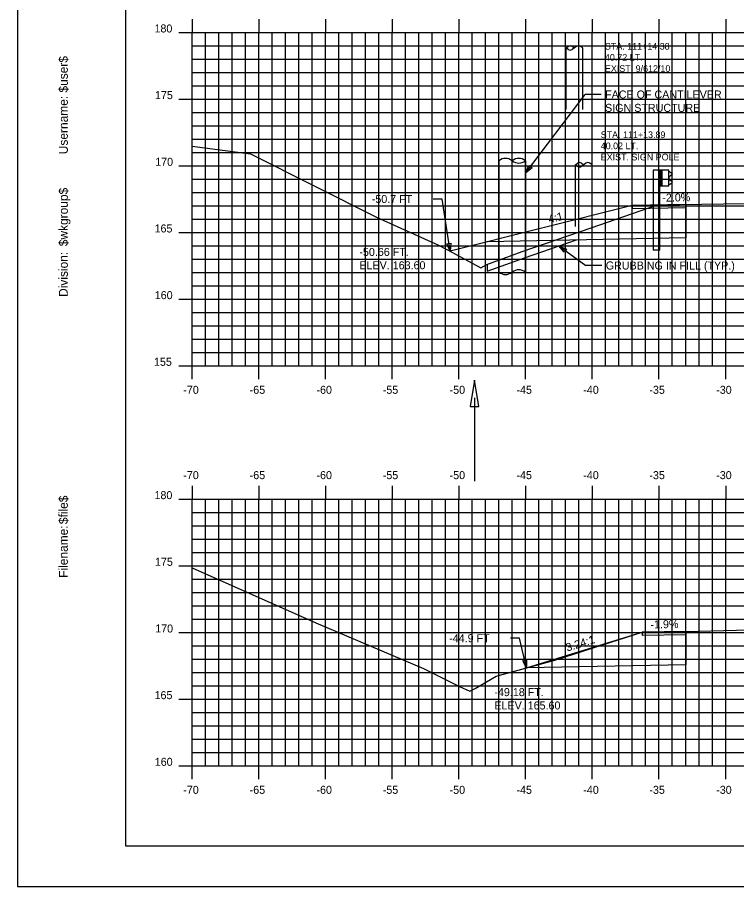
# Model space of a CAD drawing. Extents: x 1668473 to 1668643, y 337823 to 337933.
# Drawn here: x 1668472.7 to 1668526.6, y 337823.4 to 337888.6 of the extents above; entities that cross this region are included whole.
import ezdxf

# ---------------------------------------------------------------- set-up
doc = ezdxf.new("R2010")
doc.units = 0
for name, color, linetype in [('ANNOTATION', 7, 'Continuous'), ('BORDER', 7, 'Continuous'), ('D_Drainage_Ditch_Line', 7, 'Continuous'), ('D_Guardrail_Beam_Lt', 7, 'Continuous'), ('D_Roadway_Pavement', 7, 'Continuous'), ('D_Text_Monospaced', 7, 'Continuous'), ('D_Text_Standard', 7, 'Continuous'), ('Grubbing', 7, 'Continuous'), ('H_V ANNOTATION', 7, 'Continuous'), ('MAJOR', 7, 'Continuous'), ('MINOR', 7, 'Continuous'), ('PLOT BOUNDARY', 7, 'Continuous'), ('S_Roadway_Centerline', 7, 'Continuous'), ('S_Utilities_Pole_Joint', 7, 'Continuous')]:
    doc.layers.add(name, color=color, linetype=linetype)

msp = doc.modelspace()

# ---------------------------------------------------------------- linework, layer by layer
at = {"layer": 'ANNOTATION'}
for p, q in [((1668510.785, 337876.902), (1668515.247, 337882.801)), ((1668516.447, 337882.801), (1668515.247, 337882.801)), ((1668508.785, 337877.831), (1668508.785, 337869.479)), ((1668510.785, 337877.831), (1668510.785, 337869.479)), ((1668513.275, 337871.439), (1668515.297, 337869.975)), ((1668516.497, 337869.975), (1668515.297, 337869.975))]:
    msp.add_line(p, q, dxfattribs=at)
for points in [[(1668511.267, 337877.29), (1668510.785, 337876.902), (1668511.028, 337877.471)], [(1668513.673, 337870.966), (1668513.275, 337871.439), (1668513.849, 337871.209)]]:
    msp.add_lwpolyline(points, close=True, dxfattribs=at)
for centre, major_axis, start_param, end_param in [((1668509.285, 337876.346), (0, 1.664), 5.815604, 6.750767), ((1668510.285, 337876.346), (0, -1.664), 2.674011, 3.609174), ((1668510.285, 337879.317), (0, -1.664), 5.815604, 6.750767), ((1668509.285, 337870.964), (0, -1.664), 5.815604, 6.750767), ((1668510.285, 337867.994), (0, -1.664), 2.674011, 3.609174)]:
    msp.add_ellipse(centre, major_axis=major_axis, ratio=0.666667, start_param=start_param, end_param=end_param, dxfattribs=at)
at = {"layer": 'BORDER'}
for p, q in [((1668480.786, 337931.453), (1668480.786, 337826.453)), ((1668480.786, 337826.453), (1668640.786, 337826.453))]:
    msp.add_line(p, q, dxfattribs=at)
at = {"layer": 'D_Drainage_Ditch_Line'}
msp.add_line((1668506.963, 337860.055), (1668506.964, 337853.811), dxfattribs=at)
msp.add_lwpolyline([(1668506.635, 337859.399), (1668507.291, 337859.399), (1668506.963, 337861.367)], close=True, dxfattribs=at)
at = {"layer": 'D_Guardrail_Beam_Lt'}
for p, q in [((1668520.356, 337877.116), (1668520.356, 337871.116)), ((1668520.827, 337877.116), (1668520.356, 337877.116)), ((1668521.515, 337877.116), (1668520.827, 337877.116)), ((1668520.827, 337877.116), (1668520.827, 337875.949)), ((1668520.89, 337877.116), (1668520.89, 337875.949)), ((1668520.994, 337877.116), (1668520.994, 337875.949)), ((1668521.515, 337875.949), (1668521.515, 337877.116)), ((1668521.515, 337877.033), (1668521.589, 337877.018)), ((1668521.519, 337876.568), (1668521.519, 337876.498)), ((1668521.748, 337876.768), (1668521.553, 337876.632)), ((1668521.605, 337877.011), (1668521.748, 337876.911)), ((1668520.827, 337875.949), (1668521.515, 337875.949)), ((1668520.848, 337871.116), (1668520.848, 337875.949)), ((1668521.589, 337876.047), (1668521.515, 337876.033)), ((1668521.553, 337876.433), (1668521.748, 337876.297)), ((1668521.748, 337876.154), (1668521.605, 337876.054)), ((1668520.848, 337871.116), (1668520.356, 337871.116))]:
    msp.add_line(p, q, dxfattribs=at)
for centre, major_axis, start_param, end_param in [((1668521.598, 337876.568), (-0.0789, 0), 5.323254, 6.283185), ((1668521.598, 337876.498), (-0.0789, 0), 6.283185, 7.243116), ((1668521.581, 337876.977), (0.0417, 0), 0.959931, 1.376053), ((1668521.698, 337876.84), (0.0877, 0), 5.323254, 7.243116), ((1668521.581, 337876.088), (0.0417, 0), 4.907132, 5.323254), ((1668521.698, 337876.225), (0.0877, 0), 5.323254, 7.243116)]:
    msp.add_ellipse(centre, major_axis=major_axis, ratio=0.995501, start_param=start_param, end_param=end_param, dxfattribs=at)
at = {"layer": 'D_Roadway_Pavement'}
for p, q in [((1668522.785, 337874.553), (1668518.785, 337874.473)), ((1668522.785, 337874.553), (1668522.785, 337874.303)), ((1668522.785, 337874.553), (1668522.785, 337872.053)), ((1668518.785, 337874.473), (1668505.124, 337871.057)), ((1668518.785, 337874.473), (1668518.785, 337874.223)), ((1668522.785, 337874.303), (1668518.785, 337874.223)), ((1668522.785, 337872.053), (1668507.916, 337871.755)), ((1668510.845, 337839.796), (1668519.521, 337842.472)), ((1668522.785, 337842.535), (1668519.521, 337842.469)), ((1668519.521, 337842.469), (1668519.521, 337842.219)), ((1668522.785, 337842.285), (1668519.521, 337842.219)), ((1668522.785, 337842.535), (1668522.785, 337842.285)), ((1668522.785, 337842.535), (1668522.785, 337840.035)), ((1668522.785, 337840.035), (1668510.845, 337839.796))]:
    msp.add_line(p, q, dxfattribs=at)
at = {"layer": 'D_Text_Standard'}
for points in [[(1668505.124, 337871.057), (1668504.538, 337874.961), (1668503.858, 337874.961)], [(1668510.845, 337839.796), (1668510.338, 337842.026), (1668509.658, 337842.026)]]:
    msp.add_lwpolyline(points, dxfattribs=at)
for points in [[(1668505.124, 337871.057), (1668504.894, 337871.611), (1668505.181, 337871.655)], [(1668510.845, 337839.796), (1668510.574, 337840.331), (1668510.858, 337840.396)]]:
    msp.add_lwpolyline(points, close=True, dxfattribs=at)
at = {"layer": 'Grubbing'}
msp.add_line((1668507.916, 337870.074), (1668507.916, 337869.542), dxfattribs=at)
msp.add_lwpolyline([(1668507.916, 337869.542), (1668510.696, 337870.56), (1668514.593, 337871.889)], dxfattribs=at)
at = {"layer": 'MAJOR'}
for p, q in [((1668485.785, 337888.455), (1668485.785, 337887.453)), ((1668490.785, 337888.455), (1668490.785, 337887.453)), ((1668495.785, 337888.455), (1668495.785, 337887.453)), ((1668500.785, 337888.455), (1668500.785, 337887.453)), ((1668505.785, 337888.455), (1668505.785, 337887.453)), ((1668510.785, 337888.455), (1668510.785, 337887.453)), ((1668515.785, 337888.455), (1668515.785, 337887.453)), ((1668520.785, 337888.455), (1668520.785, 337887.453)), ((1668525.785, 337888.455), (1668525.785, 337887.453)), ((1668484.783, 337887.453), (1668485.785, 337887.453)), ((1668485.785, 337887.453), (1668625.785, 337887.453)), ((1668485.785, 337862.453), (1668485.785, 337887.453)), ((1668485.785, 337862.453), (1668485.785, 337887.453)), ((1668485.785, 337887.453), (1668625.785, 337887.453)), ((1668490.785, 337862.453), (1668490.785, 337887.453)), ((1668495.785, 337862.453), (1668495.785, 337887.453)), ((1668500.785, 337862.453), (1668500.785, 337887.453)), ((1668505.785, 337862.453), (1668505.785, 337887.453)), ((1668510.785, 337862.453), (1668510.785, 337887.453)), ((1668515.785, 337862.453), (1668515.785, 337887.453)), ((1668520.785, 337862.453), (1668520.785, 337887.453)), ((1668525.785, 337862.453), (1668525.785, 337887.453)), ((1668484.783, 337882.453), (1668485.785, 337882.453)), ((1668485.785, 337882.453), (1668625.785, 337882.453)), ((1668484.783, 337877.453), (1668485.785, 337877.453)), ((1668485.785, 337877.453), (1668625.785, 337877.453)), ((1668484.783, 337872.453), (1668485.785, 337872.453)), ((1668485.785, 337872.453), (1668625.785, 337872.453)), ((1668484.783, 337867.453), (1668485.785, 337867.453)), ((1668485.785, 337867.453), (1668625.785, 337867.453)), ((1668484.783, 337862.453), (1668485.785, 337862.453)), ((1668485.785, 337862.453), (1668625.785, 337862.453)), ((1668485.785, 337862.453), (1668625.785, 337862.453)), ((1668485.785, 337861.451), (1668485.785, 337862.453)), ((1668490.785, 337861.451), (1668490.785, 337862.453)), ((1668495.785, 337861.451), (1668495.785, 337862.453)), ((1668500.785, 337861.451), (1668500.785, 337862.453)), ((1668505.785, 337861.451), (1668505.785, 337862.453)), ((1668510.785, 337861.451), (1668510.785, 337862.453)), ((1668515.785, 337861.451), (1668515.785, 337862.453)), ((1668520.785, 337861.451), (1668520.785, 337862.453)), ((1668525.785, 337861.451), (1668525.785, 337862.453)), ((1668485.785, 337853.455), (1668485.785, 337852.453)), ((1668490.785, 337853.455), (1668490.785, 337852.453)), ((1668495.785, 337853.455), (1668495.785, 337852.453)), ((1668500.785, 337853.455), (1668500.785, 337852.453)), ((1668505.785, 337853.455), (1668505.785, 337852.453)), ((1668510.785, 337853.455), (1668510.785, 337852.453)), ((1668515.785, 337853.455), (1668515.785, 337852.453)), ((1668520.785, 337853.455), (1668520.785, 337852.453)), ((1668525.785, 337853.455), (1668525.785, 337852.453)), ((1668484.783, 337852.453), (1668485.785, 337852.453)), ((1668485.785, 337852.453), (1668625.785, 337852.453)), ((1668485.785, 337832.453), (1668485.785, 337852.453)), ((1668485.785, 337832.453), (1668485.785, 337852.453)), ((1668485.785, 337852.453), (1668625.785, 337852.453)), ((1668490.785, 337832.453), (1668490.785, 337852.453)), ((1668495.785, 337832.453), (1668495.785, 337852.453)), ((1668500.785, 337832.453), (1668500.785, 337852.453)), ((1668505.785, 337832.453), (1668505.785, 337852.453)), ((1668510.785, 337832.453), (1668510.785, 337852.453)), ((1668515.785, 337832.453), (1668515.785, 337852.453)), ((1668520.785, 337832.453), (1668520.785, 337852.453)), ((1668525.785, 337832.453), (1668525.785, 337852.453)), ((1668484.783, 337847.453), (1668485.785, 337847.453)), ((1668485.785, 337847.453), (1668625.785, 337847.453)), ((1668484.783, 337842.453), (1668485.785, 337842.453)), ((1668485.785, 337842.453), (1668625.785, 337842.453)), ((1668484.783, 337837.453), (1668485.785, 337837.453)), ((1668485.785, 337837.453), (1668625.785, 337837.453)), ((1668484.783, 337832.453), (1668485.785, 337832.453)), ((1668485.785, 337832.453), (1668625.785, 337832.453)), ((1668485.785, 337832.453), (1668625.785, 337832.453)), ((1668485.785, 337831.451), (1668485.785, 337832.453)), ((1668490.785, 337831.451), (1668490.785, 337832.453)), ((1668495.785, 337831.451), (1668495.785, 337832.453)), ((1668500.785, 337831.451), (1668500.785, 337832.453)), ((1668505.785, 337831.451), (1668505.785, 337832.453)), ((1668510.785, 337831.451), (1668510.785, 337832.453)), ((1668515.785, 337831.451), (1668515.785, 337832.453)), ((1668520.785, 337831.451), (1668520.785, 337832.453)), ((1668525.785, 337831.451), (1668525.785, 337832.453))]:
    msp.add_line(p, q, dxfattribs=at)
at = {"layer": 'MINOR'}
for p, q in [((1668486.785, 337862.453), (1668486.785, 337887.453)), ((1668487.785, 337862.453), (1668487.785, 337887.453)), ((1668488.785, 337862.453), (1668488.785, 337887.453)), ((1668489.785, 337862.453), (1668489.785, 337887.453)), ((1668491.785, 337862.453), (1668491.785, 337887.453)), ((1668492.785, 337862.453), (1668492.785, 337887.453)), ((1668493.785, 337862.453), (1668493.785, 337887.453)), ((1668494.785, 337862.453), (1668494.785, 337887.453)), ((1668496.785, 337862.453), (1668496.785, 337887.453)), ((1668497.785, 337862.453), (1668497.785, 337887.453)), ((1668498.785, 337862.453), (1668498.785, 337887.453)), ((1668499.785, 337862.453), (1668499.785, 337887.453)), ((1668501.785, 337862.453), (1668501.785, 337887.453)), ((1668502.785, 337862.453), (1668502.785, 337887.453)), ((1668503.785, 337862.453), (1668503.785, 337887.453)), ((1668504.785, 337862.453), (1668504.785, 337887.453)), ((1668506.785, 337862.453), (1668506.785, 337887.453)), ((1668507.785, 337862.453), (1668507.785, 337887.453)), ((1668508.785, 337862.453), (1668508.785, 337887.453)), ((1668509.785, 337862.453), (1668509.785, 337887.453)), ((1668511.785, 337862.453), (1668511.785, 337887.453)), ((1668512.785, 337862.453), (1668512.785, 337887.453)), ((1668513.785, 337862.453), (1668513.785, 337887.453)), ((1668514.785, 337862.453), (1668514.785, 337887.453)), ((1668516.785, 337862.453), (1668516.785, 337887.453)), ((1668517.785, 337862.453), (1668517.785, 337887.453)), ((1668518.785, 337862.453), (1668518.785, 337887.453)), ((1668519.785, 337862.453), (1668519.785, 337887.453)), ((1668521.785, 337862.453), (1668521.785, 337887.453)), ((1668522.785, 337862.453), (1668522.785, 337887.453)), ((1668523.785, 337862.453), (1668523.785, 337887.453)), ((1668524.785, 337862.453), (1668524.785, 337887.453)), ((1668485.785, 337886.453), (1668625.785, 337886.453)), ((1668485.785, 337886.453), (1668486.787, 337886.453)), ((1668485.785, 337885.453), (1668625.785, 337885.453)), ((1668485.785, 337885.453), (1668486.787, 337885.453)), ((1668485.785, 337884.453), (1668625.785, 337884.453)), ((1668485.785, 337884.453), (1668486.787, 337884.453)), ((1668485.785, 337883.453), (1668625.785, 337883.453)), ((1668485.785, 337883.453), (1668486.787, 337883.453)), ((1668485.785, 337881.453), (1668625.785, 337881.453)), ((1668485.785, 337881.453), (1668486.787, 337881.453)), ((1668485.785, 337880.453), (1668625.785, 337880.453)), ((1668485.785, 337880.453), (1668486.787, 337880.453)), ((1668485.785, 337879.453), (1668625.785, 337879.453)), ((1668485.785, 337879.453), (1668486.787, 337879.453)), ((1668485.785, 337878.453), (1668625.785, 337878.453)), ((1668485.785, 337878.453), (1668486.787, 337878.453)), ((1668485.785, 337876.453), (1668625.785, 337876.453)), ((1668485.785, 337876.453), (1668486.787, 337876.453)), ((1668485.785, 337875.453), (1668625.785, 337875.453)), ((1668485.785, 337875.453), (1668486.787, 337875.453)), ((1668485.785, 337874.453), (1668625.785, 337874.453)), ((1668485.785, 337874.453), (1668486.787, 337874.453)), ((1668485.785, 337873.453), (1668625.785, 337873.453)), ((1668485.785, 337873.453), (1668486.787, 337873.453)), ((1668485.785, 337871.453), (1668625.785, 337871.453)), ((1668485.785, 337871.453), (1668486.787, 337871.453)), ((1668485.785, 337870.453), (1668625.785, 337870.453)), ((1668485.785, 337870.453), (1668486.787, 337870.453)), ((1668485.785, 337869.453), (1668625.785, 337869.453)), ((1668485.785, 337869.453), (1668486.787, 337869.453)), ((1668485.785, 337868.453), (1668625.785, 337868.453)), ((1668485.785, 337868.453), (1668486.787, 337868.453)), ((1668485.785, 337866.453), (1668625.785, 337866.453)), ((1668485.785, 337866.453), (1668486.787, 337866.453)), ((1668485.785, 337865.453), (1668625.785, 337865.453)), ((1668485.785, 337865.453), (1668486.787, 337865.453)), ((1668485.785, 337864.453), (1668625.785, 337864.453)), ((1668485.785, 337864.453), (1668486.787, 337864.453)), ((1668485.785, 337863.453), (1668625.785, 337863.453)), ((1668485.785, 337863.453), (1668486.787, 337863.453)), ((1668486.785, 337832.453), (1668486.785, 337852.453)), ((1668487.785, 337832.453), (1668487.785, 337852.453)), ((1668488.785, 337832.453), (1668488.785, 337852.453)), ((1668489.785, 337832.453), (1668489.785, 337852.453)), ((1668491.785, 337832.453), (1668491.785, 337852.453)), ((1668492.785, 337832.453), (1668492.785, 337852.453)), ((1668493.785, 337832.453), (1668493.785, 337852.453)), ((1668494.785, 337832.453), (1668494.785, 337852.453)), ((1668496.785, 337832.453), (1668496.785, 337852.453)), ((1668497.785, 337832.453), (1668497.785, 337852.453)), ((1668498.785, 337832.453), (1668498.785, 337852.453)), ((1668499.785, 337832.453), (1668499.785, 337852.453)), ((1668501.785, 337832.453), (1668501.785, 337852.453)), ((1668502.785, 337832.453), (1668502.785, 337852.453)), ((1668503.785, 337832.453), (1668503.785, 337852.453)), ((1668504.785, 337832.453), (1668504.785, 337852.453)), ((1668506.785, 337832.453), (1668506.785, 337852.453)), ((1668507.785, 337832.453), (1668507.785, 337852.453)), ((1668508.785, 337832.453), (1668508.785, 337852.453)), ((1668509.785, 337832.453), (1668509.785, 337852.453)), ((1668511.785, 337832.453), (1668511.785, 337852.453)), ((1668512.785, 337832.453), (1668512.785, 337852.453)), ((1668513.785, 337832.453), (1668513.785, 337852.453)), ((1668514.785, 337832.453), (1668514.785, 337852.453)), ((1668516.785, 337832.453), (1668516.785, 337852.453)), ((1668517.785, 337832.453), (1668517.785, 337852.453)), ((1668518.785, 337832.453), (1668518.785, 337852.453)), ((1668519.785, 337832.453), (1668519.785, 337852.453)), ((1668521.785, 337832.453), (1668521.785, 337852.453)), ((1668522.785, 337832.453), (1668522.785, 337852.453)), ((1668523.785, 337832.453), (1668523.785, 337852.453)), ((1668524.785, 337832.453), (1668524.785, 337852.453)), ((1668485.785, 337851.453), (1668625.785, 337851.453)), ((1668485.785, 337851.453), (1668486.787, 337851.453)), ((1668485.785, 337850.453), (1668625.785, 337850.453)), ((1668485.785, 337850.453), (1668486.787, 337850.453)), ((1668485.785, 337849.453), (1668625.785, 337849.453)), ((1668485.785, 337849.453), (1668486.787, 337849.453)), ((1668485.785, 337848.453), (1668625.785, 337848.453)), ((1668485.785, 337848.453), (1668486.787, 337848.453)), ((1668485.785, 337846.453), (1668625.785, 337846.453)), ((1668485.785, 337846.453), (1668486.787, 337846.453)), ((1668485.785, 337845.453), (1668625.785, 337845.453)), ((1668485.785, 337845.453), (1668486.787, 337845.453)), ((1668485.785, 337844.453), (1668625.785, 337844.453)), ((1668485.785, 337844.453), (1668486.787, 337844.453)), ((1668485.785, 337843.453), (1668625.785, 337843.453)), ((1668485.785, 337843.453), (1668486.787, 337843.453)), ((1668485.785, 337841.453), (1668625.785, 337841.453)), ((1668485.785, 337841.453), (1668486.787, 337841.453)), ((1668485.785, 337840.453), (1668625.785, 337840.453)), ((1668485.785, 337840.453), (1668486.787, 337840.453)), ((1668485.785, 337839.453), (1668625.785, 337839.453)), ((1668485.785, 337839.453), (1668486.787, 337839.453)), ((1668485.785, 337838.453), (1668625.785, 337838.453)), ((1668485.785, 337838.453), (1668486.787, 337838.453)), ((1668485.785, 337836.453), (1668625.785, 337836.453)), ((1668485.785, 337836.453), (1668486.787, 337836.453)), ((1668485.785, 337835.453), (1668625.785, 337835.453)), ((1668485.785, 337835.453), (1668486.787, 337835.453)), ((1668485.785, 337834.453), (1668625.785, 337834.453)), ((1668485.785, 337834.453), (1668486.787, 337834.453)), ((1668485.785, 337833.453), (1668625.785, 337833.453)), ((1668485.785, 337833.453), (1668486.787, 337833.453))]:
    msp.add_line(p, q, dxfattribs=at)
at = {"layer": 'PLOT BOUNDARY'}
msp.add_lwpolyline([(1668472.692, 337823.394), (1668642.692, 337823.394), (1668642.692, 337933.394), (1668472.692, 337933.394)], close=True, dxfattribs=at)
at = {"layer": 'S_Roadway_Centerline'}
for points in [[(1668485.785, 337878.938), (1668490.166, 337878.346), (1668499.66, 337873.584), (1668504.205, 337871.522), (1668504.935, 337871.161), (1668507.428, 337869.795), (1668507.872, 337870.059), (1668510.53, 337871.031), (1668515.69, 337872.791), (1668520.673, 337874.519), (1668527.258, 337874.625), (1668531.072, 337874.69), (1668537.457, 337874.418), (1668540.753, 337874.279), (1668544.714, 337874.138), (1668546.319, 337874.058), (1668558.065, 337873.352), (1668558.127, 337873.381), (1668558.744, 337873.584)], [(1668485.785, 337847.299), (1668495.054, 337843.171), (1668503.126, 337839.741), (1668505.839, 337838.397), (1668506.61, 337838.053), (1668507.011, 337838.248), (1668508.574, 337839.174), (1668512.971, 337840.378), (1668515.919, 337841.328), (1668519.521, 337842.472), (1668522.777, 337842.534), (1668530.425, 337842.737), (1668537.241, 337842.485), (1668540.634, 337842.378), (1668544.16, 337842.247), (1668557.408, 337841.56), (1668557.967, 337841.525), (1668557.994, 337841.538), (1668558.009, 337841.542), (1668558.43, 337841.629)]]:
    msp.add_lwpolyline(points, dxfattribs=at)
at = {"layer": 'S_Utilities_Pole_Joint'}
for p, q in [((1668513.816, 337886.288), (1668513.972, 337886.398)), ((1668513.816, 337881.669), (1668513.819, 337886.288)), ((1668513.972, 337886.177), (1668513.816, 337886.288)), ((1668514.284, 337886.398), (1668514.441, 337886.288)), ((1668514.441, 337886.288), (1668514.284, 337886.177)), ((1668514.597, 337886.398), (1668514.441, 337886.288)), ((1668515.066, 337886.288), (1668514.91, 337886.398)), ((1668515.066, 337881.669), (1668515.069, 337886.288)), ((1668514.519, 337877.531), (1668514.675, 337877.641)), ((1668514.519, 337872.911), (1668514.522, 337877.531)), ((1668514.675, 337877.42), (1668514.519, 337877.531)), ((1668514.987, 337877.641), (1668515.144, 337877.531)), ((1668515.144, 337877.531), (1668514.987, 337877.42)), ((1668515.3, 337877.641), (1668515.144, 337877.531)), ((1668515.769, 337877.531), (1668515.613, 337877.641)), ((1668515.769, 337872.911), (1668515.772, 337877.531))]:
    msp.add_line(p, q, dxfattribs=at)
for centre, start, end in [((1668514.128, 337886.178), 90, 125.26439), ((1668514.128, 337886.178), 54.73561, 90), ((1668514.753, 337886.178), 90, 125.26439), ((1668514.753, 337886.178), 54.73561, 90), ((1668514.128, 337886.399), 234.73561, 270), ((1668514.128, 337886.399), 270, 305.26439), ((1668514.832, 337877.42), 90, 125.26439), ((1668514.832, 337877.641), 234.73561, 270), ((1668514.832, 337877.42), 54.73561, 90), ((1668514.832, 337877.641), 270, 305.26439), ((1668515.457, 337877.42), 90, 125.26439), ((1668515.457, 337877.42), 54.73561, 90)]:
    msp.add_arc(centre, 0.271, start, end, dxfattribs=at)

# ---------------------------------------------------------------- texts
at = {"layer": 'ANNOTATION'}
for s, p in [('FACE OF CANTILEVER', (1668516.747, 337882.501)), ('SIGN STRUCTURE', (1668516.747, 337881.499)), ('GRUBBING IN FILL (TYP.)', (1668516.797, 337869.675))]:
    msp.add_text(s, height=0.6, dxfattribs=at).set_placement(p)
for s, rotation, p in [('-2.0%', 1.14576, (1668521.039, 337874.756)), ('4:1', 14.03624, (1668512.565, 337873.146)), ('-1.9%', 1.09335, (1668520.153, 337842.751)), ('3.24:1', 17.14522, (1668513.906, 337841.02))]:
    msp.add_text(s, height=0.6, rotation=rotation, dxfattribs=at).set_placement(p)
at = {"layer": 'BORDER'}
for s, p in [('$user$', (1668476.471, 337882.945)), ('Username:', (1668476.471, 337878.321)), ('$wkgroup$', (1668476.471, 337871.423)), ('Division:', (1668476.471, 337867.62)), ('$file$', (1668476.471, 337850.579)), ('Filename:', (1668476.471, 337846.552))]:
    msp.add_text(s, height=0.6696, rotation=90, dxfattribs=at).set_placement(p)
at = {"layer": 'D_Text_Monospaced'}
for s, height, p in [('STA. 111+14.38', 0.49998, (1668516.732, 337886.167)), ('40.72 LT.', 0.5, (1668516.732, 337885.333)), ('EXIST. 9/612/10', 0.49998, (1668516.732, 337884.493)), ('STA. 111+13.89', 0.49998, (1668516.417, 337879.531)), ('40.02 LT.', 0.5, (1668516.417, 337878.697)), ('EXIST. SIGN POLE', 0.49998, (1668516.417, 337877.857))]:
    msp.add_text(s, height=height, dxfattribs=at).set_placement(p)
at = {"layer": 'D_Text_Standard'}
for s, p in [('-50.7 FT', (1668499.259, 337874.661)), ('-50.66 FT.', (1668498.329, 337870.693)), ('ELEV. 163.60', (1668498.329, 337869.693)), ('-44.9 FT', (1668505.06, 337841.726)), ('-49.18 FT.', (1668508.446, 337837.68)), ('-49.18 FT.', (1668508.446, 337837.68)), ('-49.18 FT.', (1668508.446, 337837.68)), ('ELEV. 165.60', (1668508.446, 337836.68)), ('ELEV. 165.60', (1668508.446, 337836.68)), ('ELEV. 165.60', (1668508.446, 337836.68))]:
    msp.add_text(s, height=0.6, dxfattribs=at).set_placement(p)
at = {"layer": 'H_V ANNOTATION'}
for s, p in [('180', (1668482.969, 337887.453)), ('175', (1668483.006, 337882.453)), ('170', (1668483.022, 337877.453)), ('165', (1668482.974, 337872.453)), ('160', (1668482.99, 337867.453)), ('155', (1668482.931, 337862.453)), ('-70', (1668485.127, 337860.353)), ('-65', (1668490.103, 337860.353)), ('-60', (1668495.111, 337860.353)), ('-55', (1668500.082, 337860.353)), ('-50', (1668505.09, 337860.353)), ('-45', (1668510.103, 337860.353)), ('-40', (1668515.111, 337860.353)), ('-35', (1668520.066, 337860.353)), ('-30', (1668525.074, 337860.353)), ('-70', (1668485.127, 337853.953)), ('-65', (1668490.103, 337853.953)), ('-60', (1668495.111, 337853.953)), ('-55', (1668500.082, 337853.953)), ('-50', (1668505.09, 337853.953)), ('-45', (1668510.103, 337853.953)), ('-40', (1668515.111, 337853.953)), ('-35', (1668520.066, 337853.953)), ('-30', (1668525.074, 337853.953)), ('180', (1668482.969, 337852.453)), ('175', (1668483.006, 337847.453)), ('170', (1668483.022, 337842.453)), ('165', (1668482.974, 337837.453)), ('160', (1668482.99, 337832.453)), ('-70', (1668485.127, 337830.353)), ('-65', (1668490.103, 337830.353)), ('-60', (1668495.111, 337830.353)), ('-55', (1668500.082, 337830.353)), ('-50', (1668505.09, 337830.353)), ('-45', (1668510.103, 337830.353)), ('-40', (1668515.111, 337830.353)), ('-35', (1668520.066, 337830.353)), ('-30', (1668525.074, 337830.353))]:
    msp.add_text(s, height=0.6, dxfattribs=at).set_placement(p)
at = {"layer": 'MAJOR'}
for p in [(1668485.781, 337862.453), (1668485.781, 337832.453)]:
    msp.add_text('-', height=0.006, dxfattribs=at).set_placement(p)

doc.saveas('drawing.dxf')
